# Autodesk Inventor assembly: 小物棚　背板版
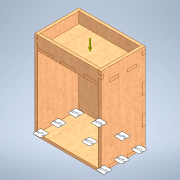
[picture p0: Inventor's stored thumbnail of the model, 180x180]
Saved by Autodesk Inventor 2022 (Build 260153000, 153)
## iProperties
Created: 2024-12
Part Number: 小物棚　背板版
Document SubType Name: Assembly
Designer: shimizu
Mass: 30.95 g
Surface Area: 349.8 cm^2
Volume: 38.6875 cm^3
Density: 0.8 g/cm^3
Author: shimizu
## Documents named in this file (6)
- C:\Users\shimizu\Documents\卒論2024\3DCAD\小物棚 - 背板版\組立図\小物棚　背板版.iam
- C:\Users\shimizu\Documents\卒論2024\3DCAD\小物棚 - 背板版\部品図\底板.ipt
- C:\Users\shimizu\Documents\卒論2024\3DCAD\小物棚 - 背板版\部品図\側板.ipt
- C:\Users\shimizu\Documents\卒論2024\3DCAD\小物棚 - 背板版\部品図\天板.ipt
- C:\Users\shimizu\Documents\卒論2024\3DCAD\小物棚 - 背板版\部品図\側板②.ipt
- C:\Users\shimizu\Documents\卒論2024\3DCAD\小物棚 - 背板版\部品図\背板.ipt
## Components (6 placed, 5 different names)
1. 底板:1 — メイト:1, フラッシュ:1, フラッシュ:2, メイト:2, フラッシュ:3, フラッシュ:4, メイト:6
2. 側板:1 — メイト:2, フラッシュ:3, フラッシュ:4, フラッシュ:5, メイト:3
3. 側板:2 — メイト:1, フラッシュ:1, フラッシュ:2, フラッシュ:6, フラッシュ:7, フラッシュ:8, フラッシュ:9
4. 天板:1 — フラッシュ:5, フラッシュ:6, メイト:3, メイト:4, メイト:5
5. 側板②:1 — メイト:4, フラッシュ:7, フラッシュ:8
6. 背板:1 — メイト:5, メイト:6, フラッシュ:9
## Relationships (15: Flush 9, Mate 6)
- メイト:1 [Mate]: 底板:1 ↔ 側板:2
- フラッシュ:1 [Flush]: 底板:1 ↔ 側板:2
- フラッシュ:2 [Flush]: 底板:1 ↔ 側板:2
- メイト:2 [Mate]: 底板:1 ↔ 側板:1
- フラッシュ:3 [Flush]: 底板:1 ↔ 側板:1
- フラッシュ:4 [Flush]: 底板:1 ↔ 側板:1
- フラッシュ:5 [Flush]: 側板:1 ↔ 天板:1
- フラッシュ:6 [Flush]: 側板:2 ↔ 天板:1
- メイト:3 [Mate]: 側板:1 ↔ 天板:1
- メイト:4 [Mate]: 天板:1 ↔ 側板②:1
- フラッシュ:7 [Flush]: 側板:2 ↔ 側板②:1
- フラッシュ:8 [Flush]: 側板:2 ↔ 側板②:1
- メイト:5 [Mate]: 天板:1 ↔ 背板:1
- メイト:6 [Mate]: 底板:1 ↔ 背板:1
- フラッシュ:9 [Flush]: 側板:2 ↔ 背板:1
## Named parameters: sa_0 = 190000 mm
